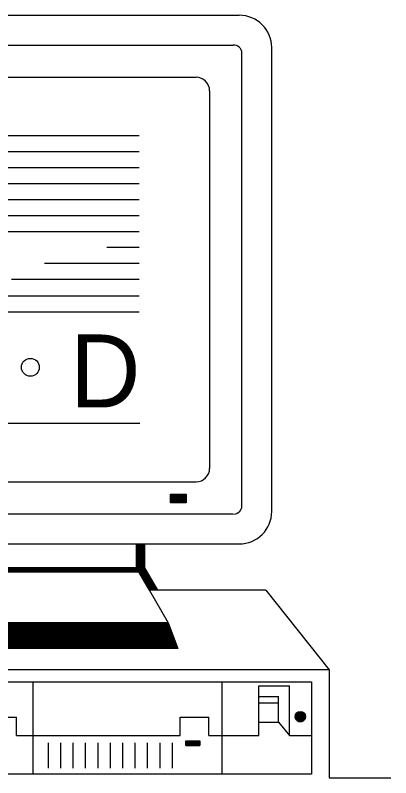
# Model space of a CAD drawing. Extents: x 18232 to 22378, y 12454 to 22381.
# Drawn here: x 22366.1879 to 22366.2516, y 22370.1457 to 22370.2752 of the extents above; entities that cross this region are included whole.
import ezdxf

# ---------------------------------------------------------------- set-up
doc = ezdxf.new("R2010")
doc.units = 0
for name, color, linetype in [('Level 1', 7, 'Continuous'), ('Level 25', 7, 'Continuous'), ('Level 50', 7, 'Continuous')]:
    doc.layers.add(name, color=color, linetype=linetype)

msp = doc.modelspace()

# ---------------------------------------------------------------- linework, layer by layer
at = {"layer": 'Level 1'}
for p, q in [((22366.14998, 22370.25479), (22366.20894, 22370.25479)), ((22366.1849, 22370.25206), (22366.20894, 22370.25206)), ((22366.1849, 22370.24934), (22366.20894, 22370.24934)), ((22366.1849, 22370.24662), (22366.20894, 22370.24662)), ((22366.1849, 22370.2439), (22366.20894, 22370.2439)), ((22366.1849, 22370.24117), (22366.20894, 22370.24117)), ((22366.14998, 22370.23844), (22366.20894, 22370.23844)), ((22366.20893, 22370.23573), (22366.20348, 22370.23573)), ((22366.20893, 22370.233), (22366.19287, 22370.233)), ((22366.20893, 22370.23028), (22366.18728, 22370.23028)), ((22366.14998, 22370.22755), (22366.20894, 22370.22755)), ((22366.14998, 22370.22482), (22366.20894, 22370.22482)), ((22366.14998, 22370.20592), (22366.20904, 22370.20592))]:
    msp.add_line(p, q, dxfattribs=at)
msp.add_circle((22366.19049, 22370.21539), 0.00152, dxfattribs=at)
at = {"layer": 'Level 25'}
for p, q in [((22366.22637, 22370.19184), (22366.22637, 22370.26874)), ((22366.23144, 22370.19089), (22366.23144, 22370.26969)), ((22366.22091, 22370.19821), (22366.22091, 22370.26236)), ((22366.13976, 22370.19592), (22366.21862, 22370.19592)), ((22366.21429, 22370.19376), (22366.21691, 22370.19376)), ((22366.21429, 22370.19369), (22366.21691, 22370.19369)), ((22366.21429, 22370.1936), (22366.21691, 22370.1936)), ((22366.21429, 22370.19351), (22366.21691, 22370.19351)), ((22366.21429, 22370.19343), (22366.21691, 22370.19343)), ((22366.21429, 22370.19335), (22366.21691, 22370.19335)), ((22366.21429, 22370.19327), (22366.21691, 22370.19327)), ((22366.21429, 22370.19319), (22366.21691, 22370.19319)), ((22366.21429, 22370.1931), (22366.21691, 22370.1931)), ((22366.21429, 22370.19302), (22366.21691, 22370.19302)), ((22366.21429, 22370.19294), (22366.21691, 22370.19294)), ((22366.21429, 22370.19285), (22366.21691, 22370.19285)), ((22366.21429, 22370.19278), (22366.21691, 22370.19278)), ((22366.21429, 22370.19269), (22366.21691, 22370.19269)), ((22366.21429, 22370.1926), (22366.21691, 22370.1926)), ((22366.21429, 22370.19253), (22366.21691, 22370.19253)), ((22366.21429, 22370.19245), (22366.21691, 22370.19245)), ((22366.13339, 22370.19047), (22366.2249, 22370.19047)), ((22366.13244, 22370.18539), (22366.22594, 22370.18539)), ((22366.20852, 22370.18134), (22366.20852, 22370.18539)), ((22366.20985, 22370.18535), (22366.20852, 22370.18535)), ((22366.20985, 22370.18527), (22366.20852, 22370.18527)), ((22366.20985, 22370.1852), (22366.20852, 22370.1852)), ((22366.20985, 22370.1851), (22366.20852, 22370.1851)), ((22366.20985, 22370.18502), (22366.20852, 22370.18502)), ((22366.20985, 22370.18494), (22366.20852, 22370.18494)), ((22366.20985, 22370.18486), (22366.20852, 22370.18486)), ((22366.20985, 22370.18478), (22366.20852, 22370.18478)), ((22366.20985, 22370.18469), (22366.20852, 22370.18469)), ((22366.20985, 22370.1846), (22366.20852, 22370.1846)), ((22366.20985, 22370.18453), (22366.20852, 22370.18453)), ((22366.20985, 22370.18445), (22366.20852, 22370.18445)), ((22366.20985, 22370.18436), (22366.20852, 22370.18436)), ((22366.20985, 22370.18428), (22366.20852, 22370.18428)), ((22366.20985, 22370.18134), (22366.20985, 22370.18539)), ((22366.20985, 22370.1842), (22366.20852, 22370.1842)), ((22366.20985, 22370.18411), (22366.20852, 22370.18411)), ((22366.20985, 22370.18403), (22366.20852, 22370.18403)), ((22366.20985, 22370.18396), (22366.20852, 22370.18396)), ((22366.20985, 22370.18386), (22366.20852, 22370.18386)), ((22366.20985, 22370.18378), (22366.20852, 22370.18378)), ((22366.20985, 22370.18371), (22366.20852, 22370.18371)), ((22366.20985, 22370.18362), (22366.20852, 22370.18362)), ((22366.20985, 22370.18354), (22366.20852, 22370.18354)), ((22366.20985, 22370.18345), (22366.20852, 22370.18345)), ((22366.20985, 22370.18337), (22366.20852, 22370.18337)), ((22366.20985, 22370.18329), (22366.20852, 22370.18329)), ((22366.20985, 22370.18321), (22366.20852, 22370.18321)), ((22366.20985, 22370.18314), (22366.20852, 22370.18314)), ((22366.20985, 22370.18304), (22366.20852, 22370.18304)), ((22366.20985, 22370.18296), (22366.20852, 22370.18296)), ((22366.20985, 22370.18287), (22366.20852, 22370.18287)), ((22366.20985, 22370.1828), (22366.20852, 22370.1828)), ((22366.20985, 22370.18272), (22366.20852, 22370.18272)), ((22366.20985, 22370.18262), (22366.20852, 22370.18262)), ((22366.20985, 22370.18254), (22366.20852, 22370.18254)), ((22366.20985, 22370.18247), (22366.20852, 22370.18247)), ((22366.20985, 22370.18239), (22366.20852, 22370.18239)), ((22366.20985, 22370.1823), (22366.20852, 22370.1823)), ((22366.20985, 22370.18222), (22366.20852, 22370.18222)), ((22366.20985, 22370.18214), (22366.20852, 22370.18214)), ((22366.20985, 22370.18205), (22366.20852, 22370.18205)), ((22366.20985, 22370.18197), (22366.20852, 22370.18197)), ((22366.20985, 22370.1819), (22366.20852, 22370.1819)), ((22366.20985, 22370.1818), (22366.20852, 22370.1818)), ((22366.20985, 22370.18172), (22366.20852, 22370.18172)), ((22366.20985, 22370.18165), (22366.20852, 22370.18165)), ((22366.20852, 22370.18134), (22366.17919, 22370.18134)), ((22366.20854, 22370.18132), (22366.17919, 22370.18132)), ((22366.2086, 22370.18124), (22366.17919, 22370.18124)), ((22366.20864, 22370.18116), (22366.17919, 22370.18116)), ((22366.20868, 22370.18107), (22366.17919, 22370.18107)), ((22366.20873, 22370.18099), (22366.17919, 22370.18099)), ((22366.20877, 22370.18091), (22366.17919, 22370.18091)), ((22366.20883, 22370.18082), (22366.17919, 22370.18082)), ((22366.20888, 22370.18075), (22366.17919, 22370.18075)), ((22366.20893, 22370.18066), (22366.17919, 22370.18066)), ((22366.20897, 22370.18057), (22366.17919, 22370.18057)), ((22366.20898, 22370.18056), (22366.17919, 22370.18056)), ((22366.20985, 22370.18156), (22366.20852, 22370.18156)), ((22366.20985, 22370.18148), (22366.20852, 22370.18148)), ((22366.20985, 22370.18139), (22366.20852, 22370.18139)), ((22366.20852, 22370.18134), (22366.21389, 22370.172)), ((22366.20987, 22370.18131), (22366.20854, 22370.18131)), ((22366.20991, 22370.18123), (22366.2086, 22370.18123)), ((22366.20997, 22370.18115), (22366.20864, 22370.18115)), ((22366.21001, 22370.18107), (22366.2087, 22370.18107)), ((22366.21005, 22370.18098), (22366.20874, 22370.18098)), ((22366.21011, 22370.1809), (22366.20878, 22370.1809)), ((22366.21015, 22370.18081), (22366.20884, 22370.18081)), ((22366.2102, 22370.18074), (22366.20888, 22370.18074)), ((22366.21025, 22370.18066), (22366.20893, 22370.18066)), ((22366.21028, 22370.18056), (22366.20897, 22370.18056)), ((22366.21035, 22370.18048), (22366.20901, 22370.18048)), ((22366.21039, 22370.18041), (22366.20908, 22370.18041)), ((22366.20985, 22370.18134), (22366.21204, 22370.17753)), ((22366.21044, 22370.18032), (22366.20912, 22370.18032)), ((22366.21048, 22370.18024), (22366.20917, 22370.18024)), ((22366.21053, 22370.18016), (22366.20921, 22370.18016)), ((22366.21058, 22370.18007), (22366.20925, 22370.18007)), ((22366.21063, 22370.17999), (22366.2093, 22370.17999)), ((22366.21068, 22370.17991), (22366.20936, 22370.17991)), ((22366.21072, 22370.17983), (22366.2094, 22370.17983)), ((22366.21077, 22370.17974), (22366.20945, 22370.17974)), ((22366.21081, 22370.17966), (22366.2095, 22370.17966)), ((22366.21086, 22370.17958), (22366.20954, 22370.17958)), ((22366.21091, 22370.1795), (22366.20959, 22370.1795)), ((22366.21095, 22370.17942), (22366.20964, 22370.17942)), ((22366.21101, 22370.17932), (22366.20968, 22370.17932)), ((22366.21105, 22370.17925), (22366.20974, 22370.17925)), ((22366.21111, 22370.17917), (22366.20978, 22370.17917)), ((22366.21115, 22370.17908), (22366.20983, 22370.17908)), ((22366.21119, 22370.17901), (22366.20988, 22370.17901)), ((22366.21124, 22370.17892), (22366.20992, 22370.17892)), ((22366.21128, 22370.17883), (22366.20997, 22370.17883)), ((22366.21134, 22370.17875), (22366.21001, 22370.17875)), ((22366.21139, 22370.17868), (22366.21005, 22370.17868)), ((22366.21143, 22370.17859), (22366.21012, 22370.17859)), ((22366.21148, 22370.1785), (22366.21016, 22370.1785)), ((22366.21152, 22370.17842), (22366.21021, 22370.17842)), ((22366.21158, 22370.17834), (22366.21025, 22370.17834)), ((22366.21162, 22370.17826), (22366.2103, 22370.17826)), ((22366.21166, 22370.17818), (22366.21035, 22370.17818)), ((22366.21172, 22370.17809), (22366.21039, 22370.17809)), ((22366.21176, 22370.17801), (22366.21044, 22370.17801)), ((22366.21181, 22370.17793), (22366.21049, 22370.17793)), ((22366.21186, 22370.17784), (22366.21054, 22370.17784)), ((22366.21191, 22370.17777), (22366.21059, 22370.17777)), ((22366.21195, 22370.17768), (22366.21063, 22370.17768)), ((22366.21199, 22370.17759), (22366.21068, 22370.17759)), ((22366.23045, 22370.17753), (22366.24116, 22370.16402)), ((22366.2139, 22370.17197), (22366.17919, 22370.17197)), ((22366.21393, 22370.17189), (22366.17919, 22370.17189)), ((22366.21397, 22370.17181), (22366.17919, 22370.17181)), ((22366.21399, 22370.17172), (22366.17919, 22370.17172)), ((22366.21402, 22370.17164), (22366.17919, 22370.17164)), ((22366.21405, 22370.17156), (22366.17919, 22370.17156)), ((22366.21409, 22370.17148), (22366.17919, 22370.17148)), ((22366.21412, 22370.1714), (22366.17919, 22370.1714)), ((22366.21414, 22370.1713), (22366.17919, 22370.1713)), ((22366.21417, 22370.17123), (22366.17919, 22370.17123)), ((22366.21421, 22370.17115), (22366.17919, 22370.17115)), ((22366.21424, 22370.17106), (22366.17919, 22370.17106)), ((22366.21426, 22370.17099), (22366.17919, 22370.17099)), ((22366.21429, 22370.1709), (22366.17919, 22370.1709)), ((22366.21434, 22370.17081), (22366.17919, 22370.17081)), ((22366.21436, 22370.17073), (22366.17919, 22370.17073)), ((22366.21439, 22370.17066), (22366.17919, 22370.17066)), ((22366.21441, 22370.17057), (22366.17919, 22370.17057)), ((22366.21445, 22370.17048), (22366.17919, 22370.17048)), ((22366.21448, 22370.1704), (22366.17919, 22370.1704)), ((22366.21451, 22370.17032), (22366.17919, 22370.17032)), ((22366.21454, 22370.17024), (22366.17919, 22370.17024)), ((22366.21458, 22370.17016), (22366.17919, 22370.17016)), ((22366.2146, 22370.17007), (22366.17919, 22370.17007)), ((22366.21463, 22370.16999), (22366.17919, 22370.16999)), ((22366.21467, 22370.16991), (22366.17919, 22370.16991)), ((22366.21469, 22370.16982), (22366.17919, 22370.16982)), ((22366.21472, 22370.16975), (22366.17919, 22370.16975)), ((22366.21475, 22370.16966), (22366.17919, 22370.16966)), ((22366.21479, 22370.16957), (22366.17919, 22370.16957)), ((22366.21481, 22370.1695), (22366.17919, 22370.1695)), ((22366.21485, 22370.16942), (22366.17919, 22370.16942)), ((22366.21487, 22370.16933), (22366.17919, 22370.16933)), ((22366.21491, 22370.16924), (22366.17919, 22370.16924)), ((22366.21494, 22370.16917), (22366.17919, 22370.16917)), ((22366.21496, 22370.16908), (22366.17919, 22370.16908)), ((22366.215, 22370.169), (22366.17919, 22370.169)), ((22366.21503, 22370.16893), (22366.17919, 22370.16893)), ((22366.21505, 22370.16883), (22366.17919, 22370.16883)), ((22366.21509, 22370.16875), (22366.17919, 22370.16875)), ((22366.21513, 22370.16867), (22366.17919, 22370.16867)), ((22366.21515, 22370.16859), (22366.17919, 22370.16859)), ((22366.21518, 22370.16851), (22366.17919, 22370.16851)), ((22366.21521, 22370.16842), (22366.17919, 22370.16842)), ((22366.21524, 22370.16833), (22366.17919, 22370.16833)), ((22366.21527, 22370.16826), (22366.17919, 22370.16826)), ((22366.2153, 22370.16818), (22366.17919, 22370.16818)), ((22366.21533, 22370.16809), (22366.17919, 22370.16809)), ((22366.21537, 22370.16801), (22366.17919, 22370.16801)), ((22366.2154, 22370.16793), (22366.17919, 22370.16793)), ((22366.21542, 22370.16784), (22366.17919, 22370.16784)), ((22366.21546, 22370.16776), (22366.17919, 22370.16776)), ((22366.21549, 22370.16769), (22366.17919, 22370.16769)), ((22366.24116, 22370.16402), (22366.17919, 22370.16402)), ((22366.24116, 22370.16402), (22366.24116, 22370.14567)), ((22366.19096, 22370.14627), (22366.19096, 22370.16195)), ((22366.22305, 22370.14627), (22366.22305, 22370.16195)), ((22366.22925, 22370.15286), (22366.22925, 22370.16127)), ((22366.22925, 22370.16127), (22366.23443, 22370.16127)), ((22366.23443, 22370.15286), (22366.23443, 22370.16127)), ((22366.22925, 22370.15945), (22366.2326, 22370.15945)), ((22366.22925, 22370.1584), (22366.2326, 22370.1584)), ((22366.2326, 22370.15508), (22366.2326, 22370.15945)), ((22366.18198, 22370.15596), (22366.18816, 22370.15596)), ((22366.18816, 22370.15286), (22366.18816, 22370.15596)), ((22366.21592, 22370.15596), (22366.22075, 22370.15596)), ((22366.21592, 22370.15286), (22366.21592, 22370.15596)), ((22366.22075, 22370.15286), (22366.22075, 22370.15596)), ((22366.23542, 22370.15605), (22366.23717, 22370.15605)), ((22366.23543, 22370.15615), (22366.23716, 22370.15615)), ((22366.23543, 22370.15598), (22366.23717, 22370.15598)), ((22366.23544, 22370.15623), (22366.23715, 22370.15623)), ((22366.23544, 22370.1559), (22366.23715, 22370.1559)), ((22366.23545, 22370.15581), (22366.23714, 22370.15581)), ((22366.23546, 22370.1563), (22366.23714, 22370.1563)), ((22366.23548, 22370.15639), (22366.2371, 22370.15639)), ((22366.23548, 22370.15573), (22366.2371, 22370.15573)), ((22366.23553, 22370.15647), (22366.23706, 22370.15647)), ((22366.23558, 22370.15656), (22366.23701, 22370.15656)), ((22366.23565, 22370.15664), (22366.23694, 22370.15664)), ((22366.23572, 22370.15672), (22366.23686, 22370.15672)), ((22366.23584, 22370.1568), (22366.23674, 22370.1568)), ((22366.23603, 22370.15687), (22366.23656, 22370.15687)), ((22366.22925, 22370.15508), (22366.2326, 22370.15508)), ((22366.2326, 22370.15508), (22366.23443, 22370.15286)), ((22366.23552, 22370.15565), (22366.23706, 22370.15565)), ((22366.23556, 22370.15556), (22366.23702, 22370.15556)), ((22366.23564, 22370.15548), (22366.23695, 22370.15548)), ((22366.23571, 22370.15541), (22366.23687, 22370.15541)), ((22366.23583, 22370.15532), (22366.23677, 22370.15532)), ((22366.23599, 22370.15523), (22366.2366, 22370.15523)), ((22366.18816, 22370.15286), (22366.21589, 22370.15286)), ((22366.21687, 22370.15195), (22366.21922, 22370.15195)), ((22366.21687, 22370.15187), (22366.21922, 22370.15187)), ((22366.22075, 22370.15286), (22366.22925, 22370.15286)), ((22366.23443, 22370.15286), (22366.23816, 22370.15286)), ((22366.19354, 22370.14727), (22366.19354, 22370.15158)), ((22366.19565, 22370.14727), (22366.19565, 22370.15158)), ((22366.19775, 22370.14727), (22366.19775, 22370.15158)), ((22366.19986, 22370.14727), (22366.19986, 22370.15158)), ((22366.20197, 22370.14727), (22366.20197, 22370.15158)), ((22366.20408, 22370.14727), (22366.20408, 22370.15158)), ((22366.20619, 22370.14727), (22366.20619, 22370.15158)), ((22366.20829, 22370.14727), (22366.20829, 22370.15158)), ((22366.21039, 22370.14727), (22366.21039, 22370.15158)), ((22366.2125, 22370.14727), (22366.2125, 22370.15158)), ((22366.21461, 22370.14727), (22366.21461, 22370.15158)), ((22366.21687, 22370.15178), (22366.21922, 22370.15178)), ((22366.21687, 22370.1517), (22366.21922, 22370.1517)), ((22366.21687, 22370.15162), (22366.21922, 22370.15162)), ((22366.21687, 22370.15154), (22366.21922, 22370.15154)), ((22366.21687, 22370.15146), (22366.21922, 22370.15146)), ((22366.21687, 22370.15136), (22366.21922, 22370.15136)), ((22366.21687, 22370.15129), (22366.21922, 22370.15129)), ((22366.21687, 22370.15121), (22366.21922, 22370.15121)), ((22366.21687, 22370.15112), (22366.21922, 22370.15112)), ((22366.24116, 22370.14567), (22366.25163, 22370.14567))]:
    msp.add_line(p, q, dxfattribs=at)
for points in [[(22366.21429, 22370.19382), (22366.21691, 22370.19382), (22366.21691, 22370.19237), (22366.21429, 22370.19237)], [(22366.20985, 22370.18539), (22366.20985, 22370.18134), (22366.21204, 22370.17753), (22366.21072, 22370.17753), (22366.20852, 22370.18134), (22366.20852, 22370.18539)], [(22366.20852, 22370.18134), (22366.20898, 22370.18056), (22366.17919, 22370.18056), (22366.17919, 22370.18134)], [(22366.21389, 22370.172), (22366.21551, 22370.16761), (22366.17919, 22370.16761), (22366.17919, 22370.172)], [(22366.12041, 22370.16195), (22366.23816, 22370.16195), (22366.23816, 22370.14627), (22366.12041, 22370.14627)], [(22366.21687, 22370.15195), (22366.21922, 22370.15195), (22366.21922, 22370.15112), (22366.21687, 22370.15112)]]:
    msp.add_lwpolyline(points, close=True, dxfattribs=at)
msp.add_circle((22366.23629, 22370.15605), 0.000875, dxfattribs=at)
for centre, start, end in [((22366.22499, 22370.26874), 0, 93.8704), ((22366.22499, 22370.19184), 270, 0)]:
    msp.add_arc(centre, 0.00138, start, end, dxfattribs=at)
at = {"layer": 'Level 50'}
for p, q in [((22366.13244, 22370.27519), (22366.22594, 22370.27519)), ((22366.13339, 22370.27011), (22366.2249, 22370.27011)), ((22366.13976, 22370.26466), (22366.21862, 22370.26466)), ((22366.23045, 22370.17753), (22366.21072, 22370.17753)), ((22366.21389, 22370.172), (22366.17919, 22370.172)), ((22366.21551, 22370.16761), (22366.17919, 22370.16761))]:
    msp.add_line(p, q, dxfattribs=at)
for centre, radius, start, end in [((22366.22594, 22370.26969), 0.0055, 0, 90), ((22366.21861, 22370.26236), 0.00229, 0, 90), ((22366.21861, 22370.19821), 0.00229, 270, 0), ((22366.22594, 22370.19089), 0.0055, 270, 0)]:
    msp.add_arc(centre, radius, start, end, dxfattribs=at)

# ---------------------------------------------------------------- texts
at = {"layer": 'Level 1'}
msp.add_text('D', height=0.0124, dxfattribs=at).set_placement((22366.1972, 22370.20857))

doc.saveas('drawing.dxf')
